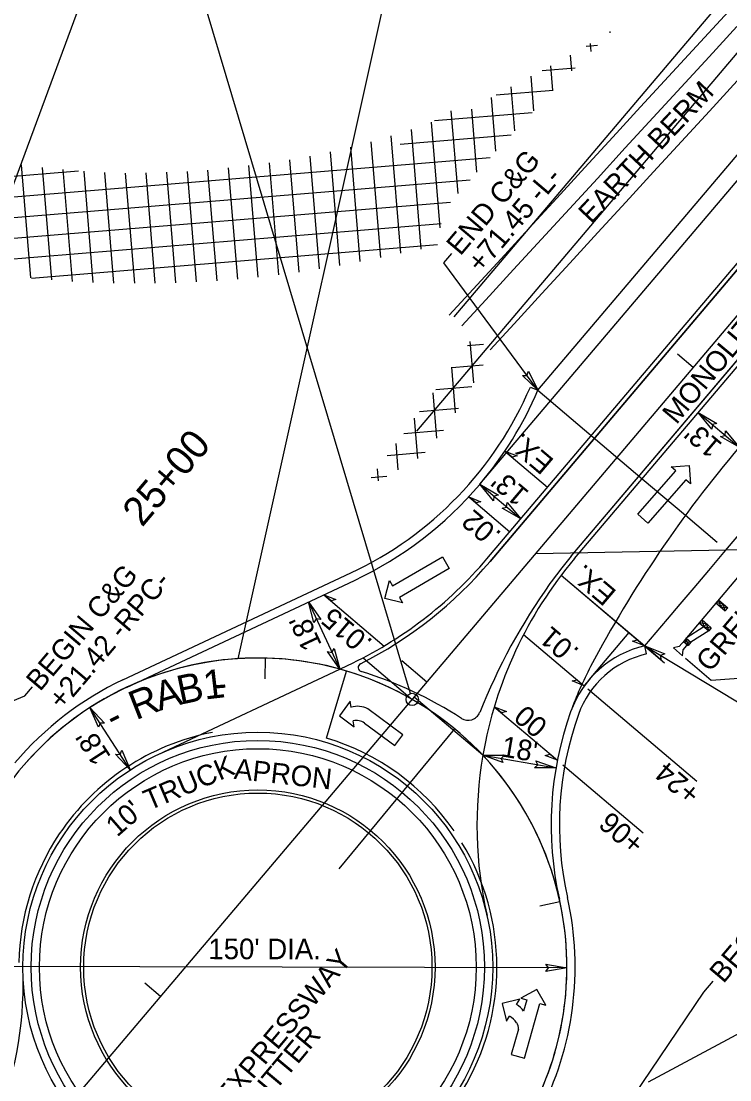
# Model space of a CAD drawing. Extents: x 1761082 to 1764358, y 421907 to 425434.
# Drawn here: x 1762165.7 to 1762337.6, y 422958.8 to 423215.6 of the extents above; entities that cross this region are included whole.
import ezdxf

# ---------------------------------------------------------------- set-up
doc = ezdxf.new("R2010")
doc.units = 0
for name, color, linetype in [('MARK HOOKS CENTER STRAIGHT LEFT TURN ARROW CELL', 7, 'Continuous'), ('MARK HOOKS STRAIGHT RIGHT TURN ARROW CELL', 7, 'Continuous'), ('MARK LEFT TURN ARROW CELL', 7, 'Continuous'), ('MARK STRAIGHT RIGHT ARROW CELL', 7, 'Continuous'), ('MARK UTURN ARROW CELL', 7, 'Continuous'), ('Prop Berm Ditch Flow Line', 7, 'Continuous'), ('Prop Conc 4in Sidewalk', 7, 'Continuous'), ('Prop Drainage Ditch Boundaries', 7, 'Continuous'), ('Prop Horizontal Alignment Tick Large', 7, 'Continuous'), ('Prop Mkg 3ft Min Skp 3ft Wide White', 7, 'Continuous'), ('Prop Mkg 3ft Min Skp 9ft White', 7, 'Continuous'), ('Prop Mkg Min Skp 6ft Yellow', 7, 'Continuous'), ('Prop Mkg Skp Wht', 7, 'Continuous'), ('Prop Mkg Solid White Diagonals', 7, 'Continuous'), ('Prop Mkg Solid White Gore Line', 7, 'Continuous'), ('Prop Mkg Solid White Lane Line', 7, 'Continuous'), ('Prop Mkg Solid White Multiple Diagonals V8i', 7, 'Continuous'), ('Prop Mkg Solid White Stop Bar', 7, 'Continuous'), ('Prop Mkg Solid Yel Skip LT', 7, 'Continuous'), ('Prop Mkg Solid Yel Skip RT', 7, 'Continuous'), ('Prop Mkg Solid Yellow Diagonals', 7, 'Continuous'), ('Prop Mkg Solid Yellow Edge Line', 7, 'Continuous'), ('Prop Mkg Solid Yellow Lane Line', 7, 'Continuous'), ('Prop Mkg Yld Lin', 7, 'Continuous'), ('Prop Mkr Yel 80ft Spc', 7, 'Continuous'), ('Scratch_Level_0', 7, 'Continuous'), ('Scratch_Level_1', 7, 'Continuous'), ('Scratch_Level_5', 7, 'Continuous')]:
    doc.layers.add(name, color=color, linetype=linetype)

msp = doc.modelspace()

# ---------------------------------------------------------------- linework, layer by layer
at = {"layer": 'MARK HOOKS CENTER STRAIGHT LEFT TURN ARROW CELL'}
for p, q in [((1762328.75, 423131.59), (1762324.94, 423134.82)), ((1762224.92, 423061.1), (1762224.8, 423056.1)), ((1762296.4, 423001.98), (1762291.51, 423000.93)), ((1762199.47, 422978.99), (1762195.66, 422982.22))]:
    msp.add_line(p, q, dxfattribs=at)
at = {"layer": 'MARK LEFT TURN ARROW CELL'}
for p, q in [((1762289.23, 423126.88), (1762291.07, 423126.1)), ((1762190.38, 423055.82), (1762245.69, 423081.78)), ((1762317.43, 423062.12), (1762316.98, 423064.07))]:
    msp.add_line(p, q, dxfattribs=at)
for centre, radius, start, end in [((1762208.3, 423161.44), 88, 295.1426, 336.8763), ((1762322.56, 423039.7), 23, 102.891, 160.4224), ((1762223.1, 422986.12), 77, 115.1426, 139.959), ((1762376.27, 423020.6), 80, 160.4224, 192.6858), ((1762223.1, 422986.12), 77, 332.4717, 12.6858)]:
    msp.add_arc(centre, radius, start, end, dxfattribs=at)
at = {"layer": 'MARK STRAIGHT RIGHT ARROW CELL'}
msp.add_line((1761294.53, 421910.78), (1762672.97, 423537.92), dxfattribs=at)
at = {"layer": 'MARK UTURN ARROW CELL'}
for points in [[(1762125.93, 423073.81), (1762189.69, 423246.02), (1762273.94, 423345.46)], [(1762260.13, 423052.53), (1762209.2, 423223.34), (1762292, 423321.08)], [(1762290.53, 423086.48), (1762412.19, 423088.84), (1762499.02, 423191.34)], [(1762317.87, 422958.33), (1762398.98, 423001.7), (1762481.78, 423099.43)]]:
    msp.add_lwpolyline(points, dxfattribs=at)
msp.add_circle((1762260.56, 423051.09), 1.5, dxfattribs=at)
at = {"layer": 'Prop Berm Ditch Flow Line'}
msp.add_lwpolyline([(1762279.48, 423135.92), (1762285.27, 423142.22), (1762292.04, 423149.59), (1762298.81, 423156.96), (1762305.58, 423164.33), (1762312.36, 423171.69), (1762319.13, 423179.06), (1762325.9, 423186.43), (1762332.67, 423193.8), (1762339.44, 423201.17)], dxfattribs=at)
at = {"layer": 'Prop Conc 4in Sidewalk'}
for p, q in [((1762308.6, 423212.83), (1762308.57, 423213.12)), ((1762302.77, 423209.6), (1762305.55, 423209.83)), ((1762303.96, 423208.27), (1762303.8, 423210.22)), ((1762299.33, 423203.6), (1762299.01, 423207.42)), ((1762292.13, 423203.71), (1762300.08, 423204.36)), ((1762294.7, 423198.83), (1762294.21, 423204.8)), ((1762290.1, 423193.89), (1762289.4, 423202.27)), ((1762280.92, 423197.76), (1762294.77, 423198.91)), ((1762285.48, 423189), (1762284.6, 423199.74)), ((1762280.87, 423184.12), (1762279.79, 423197.14)), ((1762265.98, 423191.51), (1762289.7, 423193.47)), ((1762271.69, 423173.86), (1762270.03, 423193.88)), ((1762276.28, 423179.01), (1762275.01, 423194.3)), ((1762267.36, 423165.46), (1762265.24, 423191.15)), ((1762257.84, 423159.32), (1762255.48, 423187.79)), ((1762257.65, 423185.8), (1762284.56, 423188.03)), ((1762262.77, 423160.33), (1762260.37, 423189.36)), ((1762247.97, 423157.31), (1762245.67, 423185.08)), ((1762252.91, 423158.29), (1762250.58, 423186.35)), ((1762106.52, 423168.28), (1762279.5, 423182.59)), ((1762238.08, 423155.52), (1762235.82, 423182.9)), ((1762243.03, 423156.35), (1762240.75, 423183.93)), ((1762168.03, 423153.33), (1762165.76, 423180.75)), ((1762173.08, 423152.85), (1762170.82, 423180.13)), ((1762178.13, 423152.49), (1762175.88, 423179.65)), ((1762218.22, 423153.08), (1762215.98, 423180.06)), ((1762223.2, 423153.54), (1762220.95, 423180.63)), ((1762228.17, 423154.09), (1762225.92, 423181.26)), ((1762233.13, 423154.76), (1762230.87, 423182.01)), ((1762095.7, 423172.4), (1762179.63, 423179.35)), ((1762117.73, 423164.19), (1762274.62, 423177.17)), ((1762183.17, 423152.25), (1762180.93, 423179.24)), ((1762188.2, 423152.1), (1762185.98, 423178.89)), ((1762193.22, 423152.07), (1762191.01, 423178.76)), ((1762198.23, 423152.09), (1762196.02, 423178.84)), ((1762203.24, 423152.17), (1762201.02, 423178.98)), ((1762208.24, 423152.37), (1762206.02, 423179.17)), ((1762213.23, 423152.66), (1762211.01, 423179.53)), ((1762130.44, 423160.22), (1762269.82, 423171.76)), ((1762146.78, 423156.56), (1762267.55, 423166.55)), ((1762168.19, 423153.31), (1762266.67, 423161.46)), ((1762273.99, 423136.98), (1762277.83, 423137.3)), ((1762275.49, 423127.87), (1762274.66, 423137.92)), ((1762270.14, 423131.65), (1762277.74, 423132.28)), ((1762271.07, 423120.63), (1762270.16, 423131.67)), ((1762266.26, 423126.31), (1762275.07, 423127.04)), ((1762266.56, 423114.49), (1762265.65, 423125.48)), ((1762262.36, 423120.97), (1762271.82, 423121.75)), ((1762261.96, 423109.51), (1762261.15, 423119.32)), ((1762258.51, 423115.63), (1762268.19, 423116.43)), ((1762257.17, 423106.81), (1762256.64, 423113.17)), ((1762254.52, 423110.29), (1762263.68, 423111.04)), ((1762250.58, 423104.94), (1762254.41, 423105.26)), ((1762252.37, 423104.11), (1762252.13, 423107.05))]:
    msp.add_line(p, q, dxfattribs=at)
at = {"layer": 'Prop Drainage Ditch Boundaries'}
for points in [[(1762269.56, 423144.32), (1762275.35, 423150.62), (1762282.12, 423157.99), (1762288.89, 423165.36), (1762295.66, 423172.73), (1762302.44, 423180.1), (1762309.21, 423187.47), (1762315.98, 423194.84), (1762322.75, 423202.2), (1762329.52, 423209.57), (1762336.3, 423216.94), (1762343.07, 423224.31)], [(1762272.61, 423141.74), (1762278.4, 423148.04), (1762285.17, 423155.41), (1762291.94, 423162.77), (1762298.72, 423170.14), (1762305.49, 423177.51), (1762312.26, 423184.88), (1762319.03, 423192.25), (1762325.8, 423199.62), (1762332.58, 423206.99), (1762339.35, 423214.36)]]:
    msp.add_lwpolyline(points, dxfattribs=at)
at = {"layer": 'Prop Horizontal Alignment Tick Large'}
msp.add_line((1762264.11, 423055.29), (1762258.01, 423060.46), dxfattribs=at)
at = {"layer": 'Prop Mkg 3ft Min Skp 3ft Wide White'}
msp.add_line((1761294.53, 421910.78), (1762672.97, 423537.92), dxfattribs=at)
for start, end in [(60.0363, 149.3002), (320.8368, 60.0363)]:
    msp.add_arc((1762223.1, 422986.12), 75, start, end, dxfattribs=at)
at = {"layer": 'Prop Mkg 3ft Min Skp 9ft White'}
msp.add_circle((1762223.1, 422986.12), 55, dxfattribs=at)
at = {"layer": 'Prop Mkg Skp Wht'}
for p, q in [((1762276.97, 423103.27), (1762377.21, 423221.6)), ((1762191.23, 423054.01), (1762246.54, 423079.97))]:
    msp.add_line(p, q, dxfattribs=at)
for centre, radius, start, end in [((1762208.3, 423161.44), 90, 295.1426, 319.7301), ((1762322.56, 423039.7), 25, 102.891, 160.4224), ((1762223.1, 422986.12), 75, 115.1426, 139.959), ((1762376.27, 423020.6), 82, 160.4224, 192.6858), ((1762223.1, 422986.12), 75, 332.4717, 12.6858)]:
    msp.add_arc(centre, radius, start, end, dxfattribs=at)
at = {"layer": 'Prop Mkg Solid White Diagonals'}
msp.add_line((1762477.52, 423318.34), (1762279.46, 423084.55), dxfattribs=at)
msp.add_lwpolyline([(1762299.17, 423085.85), (1762463.37, 423279.67), (1762486.6, 423307.09)], dxfattribs=at)
for radius in [53, 43]:
    msp.add_circle((1762223.1, 422986.12), radius, dxfattribs=at)
for centre, radius, start, end in [((1762202.4, 423149.84), 101, 296.8399, 319.7301), ((1762375.47, 423021.21), 100, 139.7301, 144.5723), ((1762416.22, 422992.23), 150, 144.5723, 158.2148), ((1762248.45, 423058.82), 1, 116.8399, 252.6873), ((1762218.4, 422962.4), 100, 57.2317, 72.6873), ((1762274.14, 423049.01), 3, 237.2317, 338.2148)]:
    msp.add_arc(centre, radius, start, end, dxfattribs=at)
at = {"layer": 'Prop Mkg Solid White Gore Line'}
for radius in [43, 42.25]:
    msp.add_circle((1762223.1, 422986.12), radius, dxfattribs=at)
at = {"layer": 'Prop Mkg Solid White Lane Line'}
for p, q in [((1762279.46, 423084.55), (1762477.52, 423318.34)), ((1762299.17, 423085.85), (1762486.6, 423307.09))]:
    msp.add_line(p, q, dxfattribs=at)
for centre, radius, start, end in [((1762202.4, 423149.84), 101, 296.8399, 319.7301), ((1762375.47, 423021.21), 100, 139.7301, 144.5723), ((1762416.22, 422992.23), 150, 144.5723, 158.2148), ((1762248.45, 423058.82), 1, 116.8399, 252.6873), ((1762218.4, 422962.4), 100, 57.2317, 72.6873), ((1762274.14, 423049.01), 3, 237.2317, 338.2148)]:
    msp.add_arc(centre, radius, start, end, dxfattribs=at)
at = {"layer": 'Prop Mkg Solid White Multiple Diagonals V8i'}
for p, q in [((1762270.77, 423143.91), (1762579.6, 423508.45)), ((1762261.71, 423116.2), (1762361.95, 423234.52)), ((1762198.88, 423037.72), (1762243.01, 423058.43)), ((1762239.74, 423041.68), (1762244.61, 423057.97)), ((1762242.85, 423010), (1762270.89, 423043.91))]:
    msp.add_line(p, q, dxfattribs=at)
for radius in [57, 53]:
    msp.add_circle((1762223.1, 422986.12), radius, dxfattribs=at)
for centre, radius, start, end in [((1762223.1, 422986.12), 58, 100.912, 146.1481), ((1762223.1, 422986.12), 58, 34.7546, 73.3281), ((1762376.27, 423020.6), 100, 170.2535, 192.6858), ((1762223.1, 422986.12), 75, 12.6858, 43.269), ((1762223.1, 422986.12), 58, 146.1481, 178.8788), ((1762223.1, 422986.12), 58, 328.9268, 31.3511), ((1762076.16, 422981.94), 90, 337.1611, 1.6276)]:
    msp.add_arc(centre, radius, start, end, dxfattribs=at)
at = {"layer": 'Prop Mkg Solid White Stop Bar'}
msp.add_line((1762291.07, 423126.1), (1762383.65, 423235.38), dxfattribs=at)
msp.add_lwpolyline([(1762316.98, 423064.07), (1762322.48, 423070.52), (1762325.62, 423074.22), (1762328.98, 423078.17), (1762332.54, 423082.38), (1762336.21, 423086.71), (1762339.85, 423091.02)], dxfattribs=at)
msp.add_arc((1762208.3, 423161.44), 90, 319.7301, 336.8763, dxfattribs=at)
at = {"layer": 'Prop Mkg Solid Yel Skip RT'}
for p, q in [((1762329.97, 423120.66), (1762339.89, 423112.25)), ((1762276.97, 423103.27), (1762286.89, 423094.86)), ((1762235.36, 423074.72), (1762243.01, 423058.43)), ((1762303.2, 423053.63), (1762329.62, 423031.25)), ((1762192.15, 423033.98), (1762182.37, 423049.1)), ((1762277.71, 423037.52), (1762295.45, 423034.48)), ((1762297.11, 423035.2), (1762316.61, 423018.68)), ((1762298.1, 422985.98), (1762148.1, 422986.26))]:
    msp.add_line(p, q, dxfattribs=at)
for points in [[(1762291.07, 423126.1), (1762268.22, 423156.99), (1762270.16, 423159.27)], [(1762316.98, 423064.07), (1762364.62, 423035.25), (1762365.99, 423036.87)], [(1762326.85, 423061.12), (1762333.14, 423055.79), (1762357.69, 423057.56), (1762359.06, 423059.17)], [(1762157.17, 423048.03), (1762166.56, 423051.92), (1762168.44, 423054.13)], [(1762305.74, 422942.21), (1762331.35, 422980.07), (1762333.57, 422982.69)]]:
    msp.add_lwpolyline(points, dxfattribs=at)
at = {"layer": 'Prop Mkg Solid Yellow Diagonals'}
for p, q in [((1762323.37, 423107.53), (1762327.78, 423107.85)), ((1762327.78, 423107.85), (1762328.11, 423103.37)), ((1762315.27, 423096.01), (1762324.5, 423106.54)), ((1762324.5, 423106.54), (1762323.37, 423107.53)), ((1762326.98, 423104.36), (1762317.75, 423093.83)), ((1762328.11, 423103.37), (1762326.98, 423104.36)), ((1762317.75, 423093.83), (1762315.27, 423096.01)), ((1762255.8, 423078.65), (1762267.91, 423085.66)), ((1762267.91, 423085.66), (1762269.57, 423082.81)), ((1762269.57, 423082.81), (1762257.45, 423075.79)), ((1762253.93, 423075.6), (1762255.05, 423079.95)), ((1762255.05, 423079.95), (1762255.8, 423078.65)), ((1762258.21, 423074.49), (1762253.93, 423075.6)), ((1762257.45, 423075.79), (1762258.21, 423074.49)), ((1762245.54, 423050.62), (1762242.88, 423047.11)), ((1762245.76, 423049.15), (1762245.54, 423050.62)), ((1762258.27, 423042.52), (1762249.78, 423048.79)), ((1762242.88, 423047.11), (1762246.47, 423044.4)), ((1762246.47, 423044.4), (1762246.25, 423045.87)), ((1762248.95, 423045.31), (1762256.31, 423039.87)), ((1762256.31, 423039.87), (1762258.27, 423042.52)), ((1762290.82, 422980.71), (1762286.94, 422978.59)), ((1762293, 422976.86), (1762290.82, 422980.71)), ((1762286.66, 422978.35), (1762282.36, 422977.29)), ((1762282.36, 422977.29), (1762283.42, 422972.98)), ((1762285.88, 422977.07), (1762286.66, 422978.35)), ((1762286.94, 422978.59), (1762288.38, 422978.18)), ((1762288.38, 422978.18), (1762287.6, 422975.43)), ((1762287.78, 422964), (1762291.56, 422977.27)), ((1762291.56, 422977.27), (1762293, 422976.86)), ((1762283.42, 422972.98), (1762284.19, 422974.22)), ((1762286.37, 422971.11), (1762284.61, 422964.9)), ((1762284.61, 422964.9), (1762287.78, 422964))]:
    msp.add_line(p, q, dxfattribs=at)
for centre, radius, start, end in [((1762247.34, 423044.16), 5.25, 62.217, 107.5287), ((1762247, 423042.69), 3.28, 53.541, 103.1991), ((1762283.83, 422973.12), 4.43, 31.6487, 62.5273), ((1762282.13, 422970.29), 4.43, 31.5549, 62.4085), ((1762283.85, 422971.16), 2.52, 358.733, 35.045)]:
    msp.add_arc(centre, radius, start, end, dxfattribs=at)
at = {"layer": 'Prop Mkg Solid Yellow Edge Line'}
msp.add_arc((1762223.1, 422986.12), 75, 74.6068, 115.1426, dxfattribs=at)
at = {"layer": 'Prop Mkg Solid Yellow Lane Line'}
for points in [[(1762288.74, 423130.72), (1762291.07, 423126.1), (1762287.29, 423129.68), (1762288.41, 423129.7)], [(1762333.3, 423116.69), (1762329.97, 423120.66), (1762334.47, 423118.03), (1762333.39, 423117.76)], [(1762336.56, 423116.22), (1762339.89, 423112.25), (1762335.39, 423114.88), (1762336.47, 423115.15)], [(1762280.3, 423099.3), (1762276.97, 423103.27), (1762281.47, 423100.64), (1762280.39, 423100.37)], [(1762283.57, 423098.83), (1762286.89, 423094.86), (1762282.39, 423097.49), (1762283.47, 423097.76)], [(1762236.73, 423069.73), (1762235.36, 423074.72), (1762238.36, 423070.46), (1762237.26, 423070.67)], [(1762320.87, 423060.65), (1762316.98, 423064.07), (1762321.83, 423062.15), (1762320.8, 423061.72)], [(1762241.63, 423063.42), (1762243.01, 423058.43), (1762240, 423062.69), (1762241.1, 423062.48)], [(1762184.41, 423044.34), (1762182.37, 423049.1), (1762185.92, 423045.28), (1762184.81, 423045.34)], [(1762190.11, 423038.75), (1762192.15, 423033.98), (1762188.6, 423037.8), (1762189.71, 423037.74)], [(1762282.59, 423035.79), (1762277.71, 423037.52), (1762282.92, 423037.55), (1762282.12, 423036.77)], [(1762290.57, 423036.21), (1762295.45, 423034.48), (1762290.24, 423034.45), (1762291.03, 423035.24)], [(1762293, 422986.87), (1762298.1, 422985.98), (1762292.96, 422985.08), (1762293.62, 422985.99)]]:
    msp.add_lwpolyline(points, close=True, dxfattribs=at)
at = {"layer": 'Prop Mkg Yld Lin'}
for p, q in [((1762356.81, 423101.28), (1762326.68, 423065.53)), ((1762334.22, 423074.48), (1762336.51, 423072.55)), ((1762336.01, 423074.28), (1762334.22, 423074.48)), ((1762334.86, 423075.25), (1762337.16, 423073.31)), ((1762334.86, 423075.25), (1762335.37, 423073.51)), ((1762336.01, 423074.28), (1762335.37, 423073.51)), ((1762336.51, 423072.55), (1762336.01, 423074.28)), ((1762335.37, 423073.51), (1762337.16, 423073.31)), ((1762337.16, 423073.31), (1762336.51, 423072.55)), ((1762330.16, 423069.66), (1762332.5, 423067.69)), ((1762331.97, 423069.44), (1762330.16, 423069.66)), ((1762330.8, 423070.43), (1762333.14, 423068.45)), ((1762330.8, 423070.43), (1762331.33, 423068.67)), ((1762331.97, 423069.44), (1762331.33, 423068.67)), ((1762332.5, 423067.69), (1762331.97, 423069.44)), ((1762331.33, 423068.67), (1762327, 423065.91)), ((1762332.5, 423067.69), (1762328.15, 423064.95)), ((1762331.33, 423068.67), (1762333.14, 423068.45)), ((1762333.14, 423068.45), (1762332.5, 423067.69)), ((1762326.71, 423065.46), (1762325.37, 423063.92)), ((1762326.29, 423063.11), (1762327.63, 423064.66)), ((1762326.35, 423065.15), (1762327.5, 423064.18)), ((1762326.35, 423065.15), (1762328.15, 423064.95)), ((1762327.17, 423065.06), (1762326.71, 423065.46)), ((1762327, 423065.91), (1762328.15, 423064.95)), ((1762327.5, 423064.18), (1762327, 423065.91)), ((1762327.63, 423064.66), (1762327.17, 423065.06)), ((1762328.15, 423064.95), (1762327.5, 423064.18)), ((1762328.15, 423064.95), (1762327.82, 423064.57)), ((1762325.37, 423063.92), (1762323.94, 423063.6)), ((1762323.94, 423063.6), (1762326.16, 423061.66)), ((1762326.16, 423061.66), (1762326.29, 423063.11))]:
    msp.add_line(p, q, dxfattribs=at)
at = {"layer": 'Prop Mkr Yel 80ft Spc'}
for start, end in [(60.0363, 149.3002), (320.8368, 60.0363)]:
    msp.add_arc((1762223.1, 422986.12), 75, start, end, dxfattribs=at)
at = {"layer": 'Scratch_Level_0'}
for p, q in [((1762299.96, 423085.24), (1762664.95, 423516.07)), ((1762278.7, 423085.2), (1762626.96, 423496.29)), ((1762291.07, 423126.1), (1762316.4, 423104.64)), ((1762316.4, 423104.64), (1762326.88, 423095.76)), ((1762326.88, 423095.76), (1762334.55, 423089.26)), ((1762296.74, 423081.22), (1762309.96, 423070.01)), ((1762296.74, 423081.22), (1762321.81, 423059.98)), ((1762309.96, 423070.01), (1762316.98, 423064.07)), ((1762303.49, 423055.86), (1762313.17, 423067.29)), ((1762243.01, 423058.43), (1762244.89, 423059.31)), ((1762248.65, 423061.18), (1762260.56, 423051.09)), ((1762303.49, 423055.86), (1762302.27, 423054.42)), ((1762277.71, 423037.52), (1762261.03, 423051.65))]:
    msp.add_line(p, q, dxfattribs=at)
for centre, radius, start, end in [((1762568.79, 422918.34), 300, 139.7301, 152.0251), ((1762202.4, 423149.84), 100, 295.1426, 319.7301), ((1762376.27, 423020.6), 100, 139.7301, 170.2535), ((1762376.27, 423020.6), 82, 152.0251, 160.4224), ((1762223.1, 422986.12), 75, 43.269, 74.6068)]:
    msp.add_arc(centre, radius, start, end, dxfattribs=at)
at = {"layer": 'Scratch_Level_1'}
msp.add_lwpolyline([(1762218.3, 423060.96), (1762259.15, 423244.72), (1762312.32, 423307.47)], dxfattribs=at)
at = {"layer": 'Scratch_Level_5'}
for p, q in [((1762283.06, 423111.33), (1762293.41, 423102.56)), ((1762274.29, 423100.24), (1762284.27, 423091.78)), ((1762296.74, 423081.22), (1762316.98, 423064.07)), ((1762239.1, 423076.48), (1762253.78, 423064.04)), ((1762287.6, 423066.85), (1762302.32, 423054.37)), ((1762280.47, 423049.3), (1762295.79, 423036.32))]:
    msp.add_line(p, q, dxfattribs=at)
for points in [[(1762283.06, 423111.33), (1762285.99, 423110.15), (1762284.82, 423109.83)], [(1762274.29, 423100.24), (1762277.22, 423099.06), (1762276.05, 423098.74)], [(1762239.1, 423076.48), (1762242.04, 423075.3), (1762240.87, 423074.98)], [(1762316.98, 423064.07), (1762314.05, 423065.24), (1762315.22, 423065.56)], [(1762302.32, 423054.37), (1762299.39, 423055.55), (1762300.56, 423055.87)], [(1762280.47, 423049.3), (1762283.41, 423048.12), (1762282.24, 423047.8)], [(1762295.79, 423036.32), (1762292.85, 423037.5), (1762294.02, 423037.82)]]:
    msp.add_lwpolyline(points, close=True, dxfattribs=at)

# ---------------------------------------------------------------- texts
at = {"layer": 'MARK HOOKS STRAIGHT RIGHT TURN ARROW CELL'}
for s, rotation, p in [('25+00', 49.7301, (1762195.02, 423092.68)), ('B', 11.7487, (1762204.27, 423049.78)), ('1', 6.6113, (1762210.24, 423051.04)), ('R', 21.3492, (1762193.52, 423046.01)), ('A', 16.2118, (1762199.19, 423048.25)), ('-', 4.5061, (1762212.71, 423051.41)), ('-', 26.4004, (1762188.15, 423043.31))]:
    msp.add_text(s, height=7, rotation=rotation, dxfattribs=at).set_placement(p)
at = {"layer": 'Prop Mkg Min Skp 6ft Yellow'}
for s, p in [('EX.', (1762295.23, 423109.1)), ('.02', (1762282.46, 423091.44)), ('EX.', (1762310.41, 423077.24)), ('.015', (1762251.21, 423065.28)), ('.01', (1762301.34, 423063.09)), ('00', (1762293.76, 423045.24))]:
    msp.add_text(s, height=5, rotation=139.7301, dxfattribs=at).set_placement(p)
at = {"layer": 'Prop Mkg Solid Yel Skip LT'}
for s, rotation, p in [('EARTH BERM', 46.6891, (1762304.03, 423166.26)), ('MONOLITHIC CONC. ISLAND', 50.1302, (1762324.67, 423117.59)), ('END C&G', 49.7301, (1762272.25, 423158.52)), ('+71.45 -L-', 49.7301, (1762277.25, 423154.28)), ("13'", 139.7301, (1762336.08, 423113.03)), ("13'", 139.7301, (1762289.19, 423101.36)), ('BEGIN C&G', 49.7301, (1762170.27, 423052.83)), ('+21.42 -RPC-', 49.7301, (1762175.62, 423048.3)), ("18'", 115.1426, (1762238.73, 423064.37)), ("18'", 122.8883, (1762187.6, 423037.2)), ("18'", 350.2535, (1762281.9, 423037.31)), ('TRUCK', 23.0012, (1762196.72, 423024.07)), ('APRON', 353.674, (1762217.17, 423031.84)), ('+24', 139.7301, (1762330.9, 423028.93)), ("10'", 41.0263, (1762188.95, 423017.54)), ('+06', 139.7301, (1762317.33, 423016.82)), ('BEGIN C&G', 49.7301, (1762336.08, 422981.97)), ("150' DIA.", 359.8948, (1762211.1, 422988.06)), ('EXPRESSWAY', 50.1302, (1762216.16, 422951.85)), ('GUTTER', 50.1302, (1762221.07, 422948.39))]:
    msp.add_text(s, height=5, rotation=rotation, dxfattribs=at).set_placement(p)
at = {"layer": 'Prop Mkg Yld Lin'}
msp.add_text('GREU TL-3', height=5, rotation=49.7301, dxfattribs=at).set_placement((1762332.81, 423057.45))

doc.saveas('drawing.dxf')
